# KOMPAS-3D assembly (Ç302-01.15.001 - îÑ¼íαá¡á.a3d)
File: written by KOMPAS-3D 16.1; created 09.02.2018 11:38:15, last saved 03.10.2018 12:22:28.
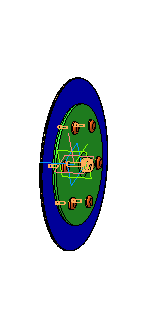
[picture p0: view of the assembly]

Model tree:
1. Массив по образцу:1  (6 pattern instances)
2. Сечение поверхностью:1  (labels: А302-01.15.000; SYSTEM_PROPERTY_ADDITIONAL_FOR:5.000000; ГОСТ Р 55739-2013)

Expressions: A2-70; М5 x 25 - A2-70; М8 x 30 - A2-70
Referenced files in Z:\Мембранные насосы\Мембранный электропривод\А302-00.00.000 - ASTRA-302 (МЭ200)\3Д ПВХ\: А302-01.15.001 - Мембрана.m3d, А302-01.15.003 - Шайба.m3d, А302-01.15.002 - Упор.m3d, А302-01.15.008 - Кольцо плоское Ф4.m3d, А302-01.15.009 - Кольцо плоское Ф4.m3d, А302-01.15.001-01- Мембрана.m3d, А302-01.15.007 - Заглушка.m3d, А302-01.15.011 - Заглушка резьбовая.m3d
Referenced files in C:\Program Files\ASCON\KOMPAS-3D V16\Libs\PartLib\DATA\vault\Methods\Kompas\3D\: PLib_Bolt_1_ISO_1100.m3d
Referenced files in Z:\2 Стандартные изделия 3D\Гайки\DIN 6927\: Гайка шестигранная самостопорящаяся с фланцем DIN 6927-M5 - A2-70.m3d
Referenced files: graphic.tdp
Referenced files in \\192.168.87.28\Konstructor_doc\Мембранные насосы\Мембранный электропривод\А302-00.00.000 - ASTRA-302 (МЭ200)\3Д ПВХ\: А302-01.15.003 - Шайба.cdw, А302-01.15.002 - Упор.cdw, А302-01.15.008 - Кольцо плоское уплотнительное 5-13-10 Ф4.cdw, А302-01.15.009 - Кольцо плоское уплотнительное Ф4.cdw
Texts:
  (-) А302-01.15.001 Мембрана
  (-) А302-01.15.003 Шайба
  (-) А302-01.15.002 Упор
  Болт с шестигранной головкой с фланцем ГОСТ Р 55739 - М5 x 25 - A2-70
  hole1
  hole2
  Болт с шестигранной головкой с фланцем ГОСТ Р  55739-М5 x 25-A2-70
  Болт с шестигранной головкой с фланцем
  (-) Болт с шестигранной головкой с фланцем ГОСТ Р 55739 - М5 x 25 - A2-70 (1)
  Гайка шестигранная самостопорящаяся с фланцем
  DIN 6927-M5-A2-70
  (-) Гайка шестигранная самостопорящаяся с фланцем DIN 6927-M5 - A2-70 (1)
  уплотнительное 5-13-10 Ф4
  Кольцо плоское /  уплотнительное 5-13-10 Ф4
  (-) А302-01.15.008 Кольцо плоское уплотнительное 5-13-10 Ф4 (1)
  Болт с шестигранной головкой с фланцем ГОСТ Р 55739 - М5 x 30 - A2-70
  (-) Болт с шестигранной головкой с фланцем ГОСТ Р 55739 - М5 x 25 - A2-70 (2)
  Болт с шестигранной головкой с фланцем ГОСТ Р 55739 - М8 x 30 - A2-70
  ГОСТ Р  55739-М8 x 30-A2-70
  (-) Болт с шестигранной головкой с фланцем ГОСТ Р 55739 - М8 x 30 - A2-70
  Кольцо плоское Ф4
  (-) А302-01.15.009 Кольцо плоское Ф4
  (-) А302-01.15.001-01 Мембрана (1)
  (-) А302-01.15.001-01 Мембрана (2)
  (-) А302-01.15.007 Заглушка (1)
  (-) А302-01.15.011 Заглушка резьбовая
